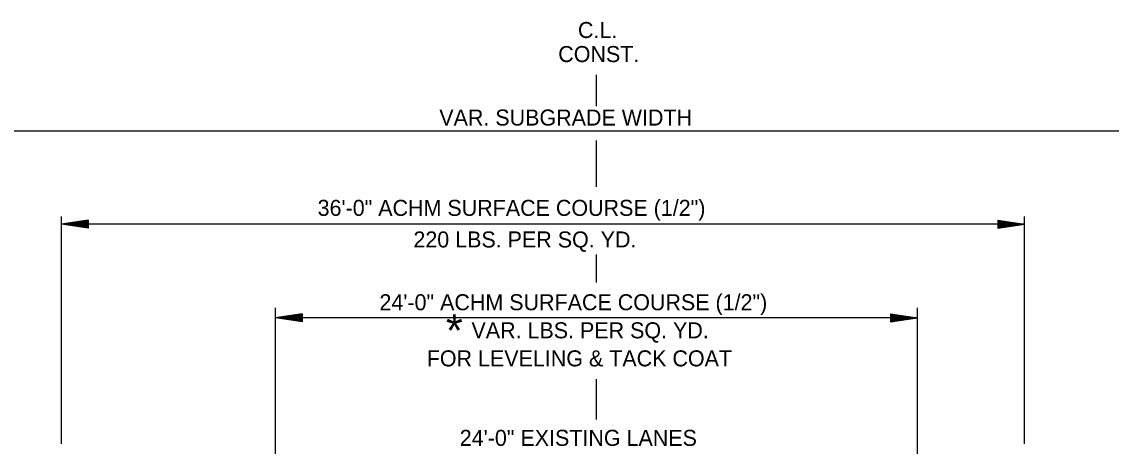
# Model space of a CAD drawing. Extents: x 1955768 to 1955917, y 566446 to 566546.
# Drawn here: x 1955818.19 to 1955858.92, y 566529.86 to 566545.75 of the extents above; entities that cross this region are included whole.
import ezdxf

# ---------------------------------------------------------------- set-up
doc = ezdxf.new("R2010")
doc.units = 0
doc.layers.add('R_Border', color=7, linetype='Continuous')
doc.layers.add('R_Grid', color=7, linetype='Continuous')

msp = doc.modelspace()

# ---------------------------------------------------------------- linework, layer by layer
at = {"layer": 'R_Grid'}
for p, q in [((1955839.673, 566542.591), (1955839.673, 566543.766)), ((1955813.423, 566541.668), (1955863.923, 566541.668)), ((1955839.673, 566539.575), (1955839.673, 566541.298)), ((1955819.673, 566529.958), (1955819.673, 566538.458)), ((1955820.673, 566538.318), (1955819.673, 566538.168)), ((1955855.673, 566538.168), (1955819.673, 566538.168)), ((1955820.673, 566538.018), (1955819.673, 566538.168)), ((1955820.673, 566538.293), (1955819.84, 566538.168)), ((1955820.673, 566538.043), (1955819.84, 566538.168)), ((1955820.673, 566538.267), (1955820.012, 566538.168)), ((1955820.673, 566538.068), (1955820.012, 566538.168)), ((1955820.673, 566538.242), (1955820.179, 566538.168)), ((1955820.673, 566538.093), (1955820.179, 566538.168)), ((1955820.673, 566538.216), (1955820.348, 566538.168)), ((1955820.673, 566538.119), (1955820.348, 566538.168)), ((1955820.673, 566538.191), (1955820.515, 566538.168)), ((1955820.673, 566538.144), (1955820.515, 566538.168)), ((1955820.673, 566538.318), (1955820.673, 566538.018)), ((1955854.673, 566538.318), (1955855.673, 566538.168)), ((1955854.673, 566538.318), (1955854.673, 566538.018)), ((1955854.673, 566538.293), (1955855.506, 566538.168)), ((1955854.673, 566538.267), (1955855.334, 566538.168)), ((1955854.673, 566538.242), (1955855.168, 566538.168)), ((1955854.673, 566538.216), (1955854.998, 566538.168)), ((1955854.673, 566538.191), (1955854.831, 566538.168)), ((1955854.673, 566538.018), (1955855.673, 566538.168)), ((1955854.673, 566538.119), (1955854.998, 566538.168)), ((1955854.673, 566538.068), (1955855.334, 566538.168)), ((1955854.673, 566538.043), (1955855.506, 566538.168)), ((1955854.673, 566538.093), (1955855.168, 566538.168)), ((1955854.673, 566538.144), (1955854.831, 566538.168)), ((1955855.673, 566529.958), (1955855.673, 566538.458)), ((1955839.673, 566535.989), (1955839.673, 566537.042)), ((1955827.673, 566523.959), (1955827.673, 566535.038)), ((1955851.672, 566520.889), (1955851.672, 566535.038)), ((1955828.673, 566534.818), (1955827.673, 566534.668)), ((1955851.672, 566534.668), (1955827.673, 566534.668)), ((1955828.673, 566534.518), (1955827.673, 566534.668)), ((1955828.673, 566534.793), (1955827.84, 566534.668)), ((1955828.673, 566534.543), (1955827.84, 566534.668)), ((1955828.673, 566534.767), (1955828.012, 566534.668)), ((1955828.673, 566534.568), (1955828.012, 566534.668)), ((1955828.673, 566534.742), (1955828.179, 566534.668)), ((1955828.673, 566534.593), (1955828.179, 566534.668)), ((1955828.673, 566534.716), (1955828.348, 566534.668)), ((1955828.673, 566534.619), (1955828.348, 566534.668)), ((1955828.673, 566534.691), (1955828.515, 566534.668)), ((1955828.673, 566534.644), (1955828.515, 566534.668)), ((1955828.673, 566534.818), (1955828.673, 566534.518)), ((1955850.672, 566534.818), (1955851.672, 566534.668)), ((1955850.672, 566534.818), (1955850.672, 566534.518)), ((1955850.672, 566534.793), (1955851.505, 566534.668)), ((1955850.672, 566534.767), (1955851.333, 566534.668)), ((1955850.672, 566534.742), (1955851.167, 566534.668)), ((1955850.672, 566534.716), (1955850.997, 566534.668)), ((1955850.672, 566534.691), (1955850.83, 566534.668)), ((1955850.672, 566534.518), (1955851.672, 566534.668)), ((1955850.672, 566534.619), (1955850.997, 566534.668)), ((1955850.672, 566534.568), (1955851.333, 566534.668)), ((1955850.672, 566534.543), (1955851.505, 566534.668)), ((1955850.672, 566534.593), (1955851.167, 566534.668)), ((1955850.672, 566534.644), (1955850.83, 566534.668)), ((1955839.673, 566530.862), (1955839.673, 566532.376))]:
    msp.add_line(p, q, dxfattribs=at)

# ---------------------------------------------------------------- texts
at = {"layer": 'R_Border'}
for s, height, p in [('C.L.', 0.6, (1955838.981, 566545.139)), ('CONST.', 0.6, (1955838.244, 566544.239)), ('VAR. SUBGRADE WIDTH', 0.6, (1955833.797, 566541.863)), ('36\'-0" ACHM SURFACE COURSE (1/2")', 0.6, (1955829.248, 566538.483)), ('220 LBS. PER SQ. YD.', 0.6, (1955832.829, 566537.301)), ('24\'-0" ACHM SURFACE COURSE (1/2")', 0.6, (1955831.56, 566534.951)), ('*', 1.2, (1955834.049, 566533.595)), ('VAR. LBS. PER SQ. YD. ', 0.6, (1955835, 566533.901)), ('FOR LEVELING & TACK COAT', 0.6, (1955833.329, 566532.851)), ('24\'-0" EXISTING LANES', 0.6, (1955834.563, 566529.876))]:
    msp.add_text(s, height=height, dxfattribs=at).set_placement(p)

doc.saveas('drawing.dxf')
